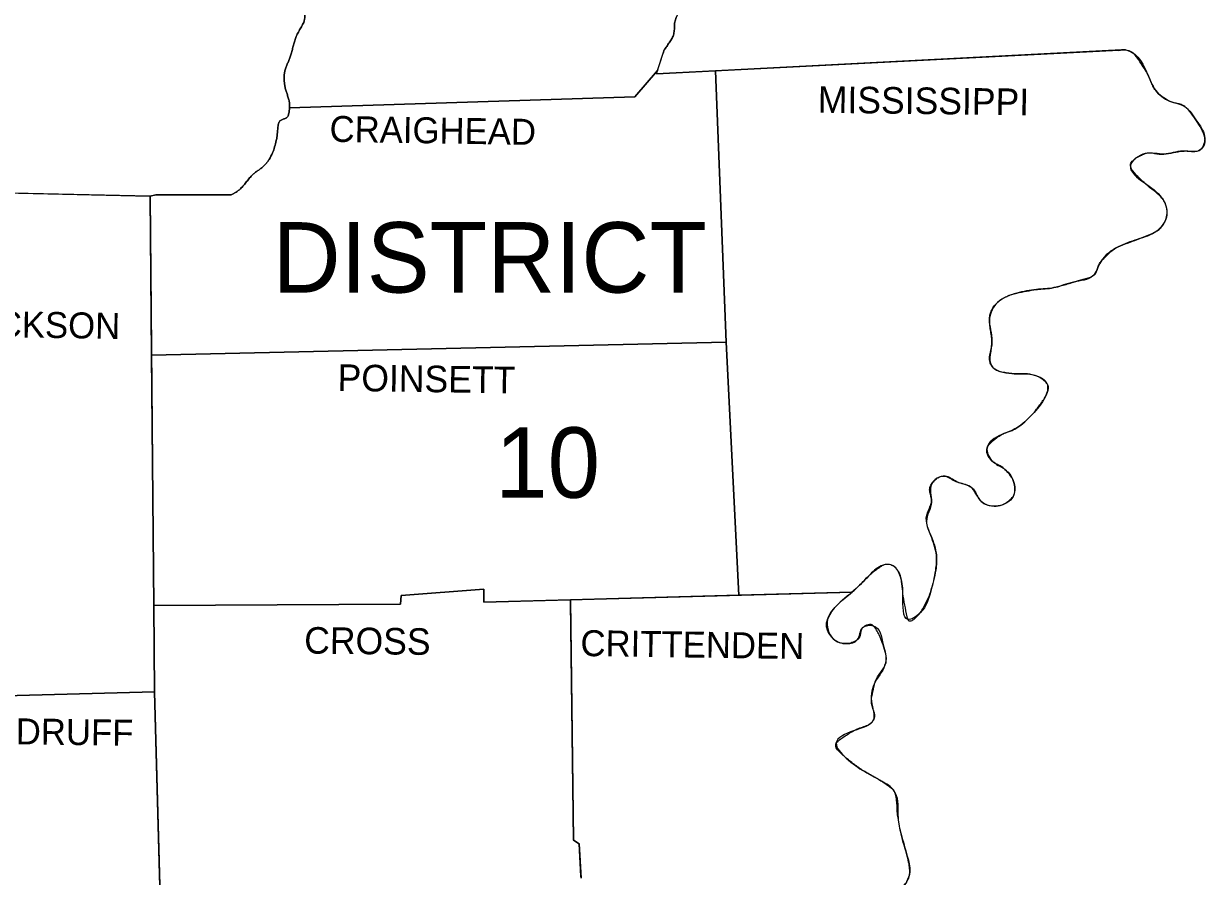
# Model space of a CAD drawing. Extents: x -28335 to 1228743, y -22428 to 152440.
# Drawn here: x 33833 to 38164, y 12816 to 15942 of the extents above; entities that cross this region are included whole.
import ezdxf

# ---------------------------------------------------------------- set-up
doc = ezdxf.new("R2010")
doc.units = 0
doc.layers.add('16', color=7, linetype='Continuous')
doc.layers.add('8', color=7, linetype='Continuous')

msp = doc.modelspace()

# ---------------------------------------------------------------- linework, layer by layer
at = {"layer": '16'}
for p, q in [((36155.9, 15769.7), (36176.5, 15832.9)), ((36408.1, 14774.6), (34301.9, 14726.6)), ((36454.1, 13846.6), (36408.1, 14774.6)), ((34301.9, 14726.6), (34309.9, 13809.5)), ((35837.1, 13829.7), (35837.2, 13820.9)), ((35837.2, 13820.9), (35837.1, 13829.7)), ((35837.2, 13820.9), (35848.5, 12948.8)), ((35848.5, 12948.8), (35837.2, 13820.9)), ((36454.1, 13846.6), (36869.5, 13858)), ((34309.9, 13809.5), (34312.6, 13492.5)), ((34312.6, 13492.5), (34332.2, 12778.8)), ((34332.2, 12778.8), (34312.6, 13492.5)), ((35848.5, 12948.8), (35868.9, 12935.2)), ((35868.9, 12935.2), (35848.5, 12948.8)), ((35868.9, 12935.2), (35875.7, 12817.4)), ((35875.7, 12817.4), (35868.9, 12935.2)), ((35875.7, 12817.4), (35876.1, 12809.9)), ((35876.1, 12809.9), (35875.7, 12817.4))]:
    msp.add_line(p, q, dxfattribs=at)
for points in [[(33611.2, 16630), (33612.7, 16582.3), (33420.1, 16564.2), (33422.4, 16500.7), (33363.5, 16498.5), (33383.9, 15329.6), (34296.8, 15309.2)], [(37871.4, 15846.1), (37857, 15845.3), (36369, 15768.9)], [(34807.8, 15632.9), (36072.8, 15673.9), (36155.9, 15769.7)], [(36369, 15768.9), (36408.1, 14774.6), (36454.1, 13846.6)], [(33705, 13796), (33716.9, 13476.6), (34312.6, 13492.5), (34309.9, 13809.5), (34301.9, 14726.6), (34296.8, 15309.2), (33793.1, 15320.5)], [(34296.8, 15309.2), (34317.2, 15313.7), (34593.5, 15313.7)], [(34309.9, 13809.5), (35214.2, 13814.2), (35216.5, 13845.9), (35520.1, 13868.5), (35520.1, 13820.9), (36454.1, 13846.6)], [(35837.1, 13829.7), (35520.1, 13820.9), (35520.1, 13868.5), (35216.5, 13845.9), (35214.2, 13814.2), (34309.9, 13809.5)], [(36869.5, 13858), (36454.1, 13846.6), (35837.1, 13829.7)], [(36869.5, 13858), (36869.5, 13858)], [(36869.5, 13858), (36869.5, 13858)], [(34312.6, 13492.5), (33716.9, 13476.6), (33705, 13796)]]:
    msp.add_lwpolyline(points, dxfattribs=at)
for points in [[(36176.5, 15832.9), (36179.3, 15841.5), (36187.6, 15855.1), (36196.9, 15868.4), (36205.9, 15881.9), (36213.2, 15895.9), (36217.3, 15912.4), (36218.3, 15930.1), (36219.7, 15947.6), (36224.6, 15963.9), (36236.3, 15982.2), (36250.3, 15999.2), (36264.5, 16016.2), (36276.7, 16034.1), (36283.3, 16049.4), (36288.7, 16065.6), (36294.9, 16081.3), (36303.8, 16095.3), (36358.2, 16156.4), (36399, 16201.7), (36411.7, 16214.5), (36425.1, 16226.5), (36438.5, 16238.6), (36451.1, 16251.6), (36456.2, 16259.1), (36459.6, 16267.5), (36463.4, 16286), (36466.8, 16304.8), (36473.7, 16321.8), (36484.8, 16338.3), (36496.2, 16354.5), (36508.3, 16370.2), (36521.3, 16385.2), (36532.9, 16397.8)], [(34857.3, 15941.7), (34860.9, 15950.3), (34863.3, 15961.9), (34863.9, 15974.1), (34864.6, 15986.3), (34867.6, 15997.8), (34876.6, 16016.1), (34886.5, 16033.8), (34908.4, 16068.1), (34921.9, 16086.4), (34936.1, 16104.1), (34950.1, 16121.9), (34962.8, 16140.6), (34970.6, 16155.9), (34976.8, 16172), (34982.9, 16188.2), (34990, 16204), (35006.3, 16232.9), (35025.5, 16260.4)], [(35025.5, 16260.4), (35006.3, 16232.9), (34990, 16204), (34982.9, 16188.2), (34976.8, 16172), (34970.6, 16155.9), (34962.8, 16140.6), (34950.1, 16121.9), (34936.1, 16104.1), (34921.9, 16086.4), (34908.4, 16068.1), (34886.5, 16033.8), (34876.6, 16016.1), (34867.6, 15997.8), (34864.6, 15986.3), (34863.9, 15974.1), (34863.3, 15961.9), (34860.9, 15950.3), (34857.3, 15941.7)], [(34794.6, 15595.7), (34795.1, 15596), (34802, 15603.7), (34804, 15610.1), (34805.6, 15616.6), (34807.5, 15629.7), (34807.9, 15642.9), (34806.5, 15655.8), (34802.9, 15669.9), (34798.3, 15684), (34793.7, 15698.2), (34790.6, 15712.4), (34788.8, 15726.5), (34787.7, 15740.8), (34788.1, 15755.1), (34790.6, 15769.1), (34795.2, 15782.8), (34800.6, 15796.3), (34806.1, 15809.8), (34811, 15823.4), (34815.7, 15839.2), (34820, 15855.1), (34824.4, 15871.1), (34829.1, 15886.9), (34836, 15903.1), (34844.6, 15918.7), (34853.5, 15934.3), (34857.3, 15941.7)], [(34857.3, 15941.7), (34853.5, 15934.3), (34844.6, 15918.7), (34836, 15903.1), (34829.1, 15886.9), (34824.4, 15871.1), (34820, 15855.1), (34815.7, 15839.2), (34811, 15823.4), (34806.1, 15809.8), (34800.6, 15796.3), (34795.2, 15782.8), (34790.6, 15769.1), (34788.1, 15755.1), (34787.7, 15740.8), (34788.8, 15726.5), (34790.6, 15712.4), (34793.7, 15698.2), (34798.3, 15684), (34802.9, 15669.9), (34806.5, 15655.8), (34807.9, 15642.9), (34807.8, 15632.9)], [(37637.3, 14981.3), (37681.2, 14994.3), (37716.5, 15004.7), (37751.4, 15017), (37761.9, 15026.4), (37768, 15040.5), (37773.1, 15055.9), (37780.8, 15069.1), (37795.2, 15084.5), (37810.1, 15099.6), (37844.3, 15123.5), (37879.3, 15137.3), (37914.5, 15150.6), (37950.9, 15165.1), (37987, 15182.4), (38001, 15193.7), (38011.6, 15208.4), (38023.2, 15241.3), (38023.9, 15256.6), (38020.9, 15272.6), (38014.6, 15288.3), (38005.1, 15302.4), (37989.3, 15318.2), (37972.6, 15331.6), (37955.7, 15344.5), (37939.4, 15359), (37908.7, 15389.5), (37896.2, 15405), (37889.6, 15420.2), (37889.4, 15423.6), (37890, 15426.9), (37893.4, 15433.6), (37906.7, 15446.3), (37925, 15457.3), (37943.9, 15465.5), (37952.4, 15467.6), (37960.9, 15468.2), (37978, 15466.3), (37995, 15463.4), (38011.9, 15463.3), (38047, 15468.9), (38082.1, 15474.6), (38097.9, 15474.8), (38113.8, 15473.4), (38129.7, 15473.7), (38145.5, 15479.1), (38148.6, 15481.1), (38151.4, 15483.5), (38156, 15488.9), (38161.9, 15501.9), (38161.4, 15528.9), (38148.9, 15557.4), (38131.9, 15585.6), (38112.2, 15613.6), (38088.9, 15637.7), (38075.7, 15644.9), (38061.1, 15648.9), (38046.2, 15652.4), (38032.3, 15658.1), (37982.4, 15696.6), (37972.1, 15712.6), (37964.6, 15729.9), (37957.5, 15747.6), (37948.5, 15764.5), (37932.6, 15789.7), (37915.8, 15814.5), (37896.1, 15834.8), (37871.4, 15846.1)], [(34593.5, 15313.7), (34602.9, 15318.6), (34611.6, 15323.8), (34627.5, 15336.4), (34639.5, 15349.1), (34650.4, 15362.5), (34661.2, 15375.9), (34672.8, 15388.5), (34683.2, 15397.2), (34694.4, 15405.2), (34705.5, 15413.3), (34715.9, 15422.5), (34724.9, 15432.8), (34732.7, 15443.7), (34745.3, 15467.8), (34753, 15490.3), (34758.9, 15513.1), (34761.8, 15529.4), (34763.4, 15546), (34765, 15562.6), (34766.2, 15570.7), (34768, 15578.8), (34774.1, 15586.5), (34784.5, 15591.2), (34794.6, 15595.7)], [(37249.7, 14264.1), (37253, 14262.7), (37302.8, 14244.5), (37315.8, 14233.6), (37324.7, 14217.8), (37333.5, 14201.2), (37345.9, 14187.9), (37374.9, 14175.3), (37404.8, 14174.3), (37433.6, 14185.5), (37446.9, 14195.3), (37459.2, 14208.3), (37463.7, 14255.9), (37429.7, 14308), (37418.5, 14317), (37406.1, 14323.8), (37393.6, 14330.7), (37382.1, 14339.7), (37365.6, 14363.3), (37364, 14387.3), (37373.6, 14400.7), (37386.1, 14413.2), (37416.1, 14434.8), (37430.3, 14441.7), (37444.9, 14447), (37459.3, 14452.4), (37472.7, 14459.7), (37529.4, 14509.6), (37542.7, 14524.6), (37554.9, 14540.3), (37576.9, 14573), (37588, 14598), (37588.7, 14611.1), (37583.7, 14622.8), (37577.3, 14629.8), (37570.3, 14635.9), (37554.9, 14645.5), (37520.3, 14656.8), (37503.9, 14658.5), (37487.5, 14658.2), (37471, 14657.8), (37454.6, 14659.1), (37434, 14661.9), (37413.3, 14665.6), (37394.6, 14673.4), (37379.9, 14688.5), (37377, 14694), (37374.9, 14699.5), (37373, 14710.5), (37375, 14732.6), (37380, 14754.8), (37382.1, 14776.9), (37379.9, 14797.8), (37376.8, 14818.8), (37374, 14839.8), (37373.1, 14860.7), (37375.2, 14876.7), (37381, 14892), (37402.5, 14919.6), (37410.8, 14926.5), (37419.1, 14932.5), (37436.3, 14941.9), (37454.1, 14948.6), (37472.7, 14953.6), (37508.9, 14961.1), (37545.2, 14967.2), (37561.1, 14968.8), (37577.1, 14969.9), (37608.7, 14974), (37637.3, 14981.3)], [(36869.5, 13858), (36883.8, 13870.8), (36935.9, 13922.9), (36958.8, 13941.4), (36971, 13949.4), (36983.4, 13956.9), (37001.5, 13961), (37019.7, 13954.6), (37029.4, 13945.8), (37037.4, 13936.1), (37043.3, 13925.4), (37046.9, 13913.8), (37049.7, 13896.3), (37051.7, 13878.7), (37055.9, 13843.6), (37063.4, 13799.9), (37074.1, 13757.5), (37077.1, 13753.3), (37082.1, 13752.5), (37095.2, 13758.3), (37119.4, 13782.4), (37130.9, 13801.7), (37141.4, 13821.1), (37150.5, 13841), (37157.9, 13861.7), (37176, 13938.7), (37178.3, 13993.1), (37157.9, 14065.6), (37142, 14117.7), (37141.8, 14135.1), (37147.4, 14152.7), (37154.9, 14170.3), (37160.1, 14187.9), (37160.4, 14195.9), (37159.3, 14204.1), (37155.4, 14220.6), (37153.8, 14237.2), (37160.1, 14253.6), (37165.6, 14260.6), (37171.5, 14267), (37183.8, 14277.5), (37210, 14283.1), (37229.8, 14274.2), (37249.7, 14264.1)], [(36983.4, 13664.6), (36968.6, 13701.9), (36958.9, 13719.1), (36953.3, 13727.2), (36947.2, 13734.9), (36938.9, 13739.2), (36928.2, 13738.4), (36917.4, 13734.1), (36908.7, 13728.1), (36902.8, 13717.9), (36900, 13705.2), (36896.4, 13692.6), (36888.3, 13682.8), (36878.7, 13677.2), (36869, 13672.9), (36859.4, 13670.2), (36849.8, 13669.2), (36837.3, 13669.8), (36824.8, 13672.5), (36812.4, 13678), (36799.9, 13687.3), (36795.9, 13691.3), (36792.1, 13695.5), (36785.9, 13704.2), (36777.8, 13722.4), (36775.7, 13740.7), (36779.6, 13757.5), (36786.8, 13772.4), (36795.6, 13787.1), (36818.1, 13814.2), (36843.7, 13836.6), (36869.5, 13858)], [(36613.9, 12408.7), (36641.4, 12412.1), (36668.6, 12418.8), (36673.4, 12421.1), (36678, 12423.8), (36686.1, 12430.5), (36699.3, 12447.2), (36709.6, 12466.8), (36718.4, 12486.7), (36743.3, 12545.6), (36768.2, 12600), (36802.2, 12663.4), (36836.2, 12726.8), (36856, 12753.9), (36883.8, 12772.1), (36890.9, 12774), (36898.3, 12774.8), (36913.2, 12773.9), (36942.7, 12767.6), (36955.1, 12764), (36967.6, 12759.3), (36980, 12754.8), (36992.5, 12751.8), (37004.4, 12751.1), (37016.3, 12753), (37028.2, 12757.7), (37040.1, 12765.3), (37049.1, 12772.9), (37057.2, 12780.7), (37070.2, 12797), (37078.3, 12814.5), (37080.8, 12833.3), (37079.9, 12847.5), (37078, 12861.7), (37071.8, 12889.9), (37049.1, 12971.5), (37043.2, 13000.9), (37037.8, 13030.4), (37035.1, 13053.5), (37034, 13076.9), (37031.9, 13100.2), (37026.5, 13123.3), (37023.4, 13129.9), (37019.3, 13135.7), (37008.7, 13145.7), (36983.4, 13161.8), (36966.5, 13171.7), (36949.4, 13181), (36932.3, 13190.3), (36915.5, 13200.3), (36880.9, 13223.9), (36847.5, 13250.1), (36818.7, 13277.3), (36809.7, 13291.9), (36811.3, 13304.5), (36817, 13310.8), (36823.7, 13316.8), (36839.7, 13328.3), (36857.3, 13339.1), (36874.7, 13349.8), (36883.8, 13354.7), (36893.2, 13358.5), (36912.6, 13365), (36931.2, 13373.5), (36947.2, 13388.3), (36949.8, 13392.5), (36951.5, 13396.7), (36952.6, 13405.3), (36948.8, 13423), (36942.5, 13440.9), (36940.4, 13458.5), (36945.8, 13493.7), (36954, 13528.7), (36962.5, 13547.1), (36974.2, 13564.2), (36985.4, 13581.1), (36992.5, 13599), (36983.4, 13664.6)]]:
    msp.add_spline(points, degree=3, dxfattribs=at)
at = {"layer": '8'}
for p, q in [((36152.1, 15757.7), (36176.5, 15832.9)), ((36152.1, 15757.7), (36155.9, 15769.7)), ((36369, 15768.9), (36152.1, 15757.7)), ((36408.1, 14774.6), (36369, 15768.9)), ((34296.8, 15309.2), (34301.9, 14726.6)), ((34301.9, 14726.6), (36408.1, 14774.6))]:
    msp.add_line(p, q, dxfattribs=at)
for points in [[(33229.3, 17459.6), (33220.8, 17391), (33266.1, 17384.2), (33263.8, 17357), (33315.9, 17345.7), (33320.4, 17309.4), (33345.4, 17293.6), (33352.2, 17184.8), (33481.3, 17171.2), (33481.3, 17073.8), (33528.9, 17067), (33528.9, 17028.5), (33569.6, 17017.2), (33567.4, 16885.8), (33603.6, 16879), (33612.7, 16582.3), (33420.1, 16564.2), (33422.4, 16500.7), (33363.5, 16498.5), (33383.9, 15329.6), (34296.8, 15309.2), (34312.6, 13492.5), (33716.9, 13476.6), (33705, 13796)], [(36152.1, 15757.7), (37871.4, 15846.1)], [(36155.9, 15769.7), (36072.8, 15673.9), (34807.8, 15632.9)], [(34807.8, 15632.9), (36072.8, 15673.9), (36155.9, 15769.7)], [(36369, 15768.9), (36408.1, 14774.6), (36454.1, 13846.6)], [(34593.5, 15313.7), (34317.2, 15313.7), (34296.8, 15309.2)], [(34593.5, 15313.7), (34317.2, 15313.7), (34296.8, 15309.2)], [(36408.1, 14774.6), (34301.9, 14726.6)], [(34309.9, 13809.5), (35214.2, 13814.2), (35216.5, 13845.9), (35520.1, 13868.5), (35520.1, 13820.9), (36869.5, 13858)], [(35837.1, 13829.7), (35848.5, 12948.8), (35868.9, 12935.2), (35876.1, 12809.9)], [(35837.2, 13820.9), (35848.5, 12948.8), (35868.9, 12935.2), (35875.7, 12817.4)], [(35837.2, 13820.9), (35848.5, 12948.8), (35868.9, 12935.2), (35875.7, 12817.4)], [(35837.2, 13820.9), (35848.5, 12948.8), (35868.9, 12935.2), (35875.7, 12817.4)], [(35837.2, 13820.9), (35848.5, 12948.8), (35868.9, 12935.2), (35875.7, 12817.4)], [(34312.6, 13492.5), (34346.6, 12251.1), (33807.5, 12248.9), (33805.2, 12199), (33648.9, 12190), (33635.3, 11931.7), (33420.5, 11931.7)]]:
    msp.add_lwpolyline(points, dxfattribs=at)
for points in [[(36695.7, 17526.9), (36697.7, 17501.9), (36700.3, 17476.9), (36703.5, 17452.1), (36707.1, 17427.2), (36712.4, 17413.2), (36721.5, 17400.5), (36731.4, 17388.2), (36738.8, 17375.1), (36741.7, 17352.1), (36738.8, 17327.3), (36737.1, 17302.7), (36738.8, 17291), (36743.3, 17280), (36760.5, 17257.7), (36781.8, 17239.2), (36798, 17228.4), (36814.8, 17218.9), (36831.5, 17209.4), (36847.5, 17198.4), (36880.2, 17169.4), (36894.2, 17152.5), (36900.5, 17143), (36906.4, 17132.7), (36914.6, 17113.6), (36919.4, 17094.2), (36921.1, 17074.9), (36920, 17055.7), (36916.1, 17035.9), (36910.5, 17016.2), (36905.1, 16996.4), (36901.9, 16976.4), (36900.6, 16954.4), (36899.9, 16932.3), (36899, 16910.2), (36897.4, 16888.1), (36888.3, 16811.1), (36884, 16775.6), (36880.5, 16758.1), (36878, 16749.4), (36874.7, 16740.8), (36851.1, 16709.5), (36820.3, 16684.2), (36807.3, 16673.9), (36794.1, 16664), (36781, 16653.9), (36768.2, 16643.4), (36720.7, 16595.9), (36711.8, 16583.7), (36704.1, 16570.5), (36696.2, 16557.6), (36686.7, 16546), (36627.8, 16491.7), (36568.9, 16435), (36521.3, 16385.2), (36508.3, 16370.2), (36496.2, 16354.5), (36484.8, 16338.3), (36473.7, 16321.8), (36466.8, 16304.8), (36463.4, 16286), (36459.6, 16267.5), (36456.2, 16259.1), (36451.1, 16251.6), (36438.5, 16238.6), (36425.1, 16226.5), (36411.7, 16214.5), (36399, 16201.7), (36358.2, 16156.4), (36303.8, 16095.3), (36294.9, 16081.3), (36288.7, 16065.6), (36283.3, 16049.4), (36276.7, 16034.1), (36264.5, 16016.2), (36250.3, 15999.2), (36236.3, 15982.2), (36224.6, 15963.9), (36219.7, 15947.6), (36218.3, 15930.1), (36217.3, 15912.4), (36213.2, 15895.9), (36205.9, 15881.9), (36196.9, 15868.4), (36187.6, 15855.1), (36179.3, 15841.5), (36176.5, 15832.9)], [(35025.5, 16260.4), (35006.3, 16232.9), (34990, 16204), (34982.9, 16188.2), (34976.8, 16172), (34970.6, 16155.9), (34962.8, 16140.6), (34950.1, 16121.9), (34936.1, 16104.1), (34921.9, 16086.4), (34908.4, 16068.1), (34886.5, 16033.8), (34876.6, 16016.1), (34867.6, 15997.8), (34864.6, 15986.3), (34863.9, 15974.1), (34863.3, 15961.9), (34860.9, 15950.3), (34853.5, 15934.3), (34844.6, 15918.7), (34836, 15903.1), (34829.1, 15886.9), (34824.4, 15871.1), (34820, 15855.1), (34815.7, 15839.2), (34811, 15823.4), (34806.1, 15809.8), (34800.6, 15796.3), (34795.2, 15782.8), (34790.6, 15769.1), (34788.1, 15755.1), (34787.7, 15740.8), (34788.8, 15726.5), (34790.6, 15712.4), (34793.7, 15698.2), (34798.3, 15684), (34802.9, 15669.9), (34806.5, 15655.8), (34807.9, 15642.9), (34807.5, 15629.7), (34805.6, 15616.6), (34804, 15610.1), (34802, 15603.7), (34795.1, 15596), (34784.5, 15591.2), (34774.1, 15586.5), (34768, 15578.8), (34766.2, 15570.7), (34765, 15562.6), (34763.4, 15546), (34761.8, 15529.4), (34758.9, 15513.1), (34753, 15490.3), (34745.3, 15467.8), (34732.7, 15443.7), (34724.9, 15432.8), (34715.9, 15422.5), (34705.5, 15413.3), (34694.4, 15405.2), (34683.2, 15397.2), (34672.8, 15388.5), (34661.2, 15375.9), (34650.4, 15362.5), (34639.5, 15349.1), (34627.5, 15336.4), (34611.6, 15323.8), (34602.9, 15318.6), (34593.5, 15313.7)], [(37846.5, 15843.8), (37871.4, 15846.1), (37948.5, 15764.5), (37982.4, 15696.6), (38032.3, 15658.1), (38088.9, 15637.7), (38131.9, 15585.6), (38161.4, 15528.9), (38145.5, 15479.1), (38082.1, 15474.6), (38011.9, 15463.3), (37943.9, 15465.5), (37889.6, 15420.2), (37939.4, 15359), (38005.1, 15302.4), (38023.2, 15241.3), (37987, 15182.4), (37914.5, 15150.6), (37844.3, 15123.5), (37780.8, 15069.1), (37751.4, 15017), (37681.2, 14994.3), (37608.7, 14974), (37545.2, 14967.2), (37472.7, 14953.6), (37402.5, 14919.6), (37373.1, 14860.7), (37382.1, 14776.9), (37379.9, 14688.5), (37454.6, 14659.1), (37520.3, 14656.8), (37583.7, 14622.8), (37576.9, 14573), (37529.4, 14509.6), (37472.7, 14459.7), (37416.1, 14434.8), (37364, 14387.3), (37382.1, 14339.7), (37429.7, 14308), (37463.7, 14255.9), (37459.2, 14208.3), (37404.8, 14174.3), (37345.9, 14187.9), (37302.8, 14244.5), (37253, 14262.7), (37210, 14283.1), (37160.1, 14253.6), (37160.1, 14187.9), (37142, 14117.7), (37157.9, 14065.6), (37178.3, 13993.1), (37176, 13938.7), (37157.9, 13861.7), (37119.4, 13782.4), (37074.1, 13757.5), (37055.9, 13843.6), (37046.9, 13913.8), (37019.7, 13954.6), (36983.4, 13956.9), (36935.9, 13922.9), (36883.8, 13870.8), (36818.1, 13814.2), (36779.6, 13757.5), (36799.9, 13687.3), (36849.8, 13669.2), (36888.3, 13682.8), (36908.7, 13728.1), (36947.2, 13734.9), (36983.4, 13664.6)], [(34794.6, 15595.7), (34784.5, 15591.2), (34774.1, 15586.5), (34768, 15578.8), (34766.2, 15570.7), (34765, 15562.6), (34763.4, 15546), (34761.8, 15529.4), (34758.9, 15513.1), (34753, 15490.3), (34745.3, 15467.8), (34732.7, 15443.7), (34724.9, 15432.8), (34715.9, 15422.5), (34705.5, 15413.3), (34694.4, 15405.2), (34683.2, 15397.2), (34672.8, 15388.5), (34661.2, 15375.9), (34650.4, 15362.5), (34639.5, 15349.1), (34627.5, 15336.4), (34611.6, 15323.8), (34602.9, 15318.6), (34593.5, 15313.7)], [(34807.8, 15632.9), (34807.5, 15629.7), (34805.6, 15616.6), (34804, 15610.1), (34802, 15603.7), (34795.1, 15596), (34794.6, 15595.7)], [(36983.4, 13664.6), (36992.5, 13599), (36954, 13528.7), (36940.4, 13458.5), (36947.2, 13388.3), (36874.7, 13349.8), (36811.3, 13304.5), (36847.5, 13250.1), (36915.5, 13200.3), (36983.4, 13161.8), (37026.5, 13123.3), (37037.8, 13030.4), (37049.1, 12971.5), (37071.8, 12889.9), (37080.8, 12833.3), (37040.1, 12765.3), (36992.5, 12751.8), (36942.7, 12767.6), (36883.8, 12772.1), (36836.2, 12726.8), (36802.2, 12663.4), (36768.2, 12600), (36743.3, 12545.6), (36718.4, 12486.7), (36668.6, 12418.8), (36607.4, 12407.4), (36534.9, 12389.3), (36491.9, 12339.5), (36498.7, 12255.7), (36539.4, 12199), (36571.2, 12128.8), (36593.8, 12067.6), (36582.5, 11990.6), (36550.8, 11934), (36510, 11900), (36491.9, 11827.5), (36462.4, 11773.2), (36435.2, 11755), (36380.9, 11759.6), (36322, 11770.9), (36272.1, 11766.4), (36224.6, 11741.4), (36177, 11757.3), (36127.2, 11811.7), (36086.4, 11852.4), (36041.1, 11868.3), (35993.5, 11843.4), (35984.4, 11768.6), (36007.1, 11691.6), (36027.5, 11587.4), (36007.1, 11524), (36000.3, 11419.8)]]:
    msp.add_spline(points, degree=3, dxfattribs=at)

# ---------------------------------------------------------------- texts
for s, height, rotation, p in [('MISSISSIPPI', 97.394, 359.3097, (36743.3, 15615)), ('CRAIGHEAD', 95.15, 359.1159, (34953.7, 15508.6)), ('JACKSON', 95.12, 359.1352, (33585.5, 14795)), ('POINSETT', 97.4, 359.1987, (34983.2, 14595.7)), ('CROSS', 97.4, 359.384, (34860.9, 13632.9)), ('CRITTENDEN', 95.15, 359.213, (35873.4, 13623.9)), ('WOODRUFF', 95.12, 359.2748, (33485.8, 13304.5))]:
    msp.add_text(s, height=height, rotation=rotation, dxfattribs=at).set_placement(p)
for s, p in [('DISTRICT', (34745.3, 14955.8)), ('10', (35561.5, 14203.8))]:
    msp.add_text(s, height=258.24, dxfattribs=at).set_placement(p)

doc.saveas('drawing.dxf')
